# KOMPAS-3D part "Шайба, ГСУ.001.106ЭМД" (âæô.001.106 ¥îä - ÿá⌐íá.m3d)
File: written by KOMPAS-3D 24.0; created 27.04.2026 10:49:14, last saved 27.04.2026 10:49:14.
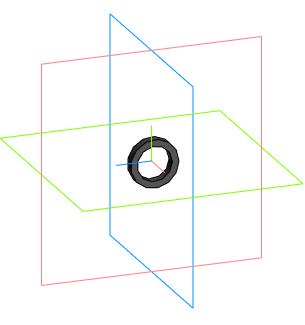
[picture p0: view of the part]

Document properties: Автор: USG_411; Полное имя файла: C:\Users\USG_411\Desktop\ГМ2704_411-15\Двигатель мясорубки\ГСУ.001.106 ЭМД - Шайба.m3d

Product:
- Part/product: Шайба  | designation ГСУ.001.106ЭМД
    Масса: 0.000703

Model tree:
1. Эскиз:1
2. Элемент выдавливания:1
     Толщина стенки 2 = 1.5; Расстояние 1 = 2

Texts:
  ГСУ.001.106
  ГСУ.001.106 ЭМД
